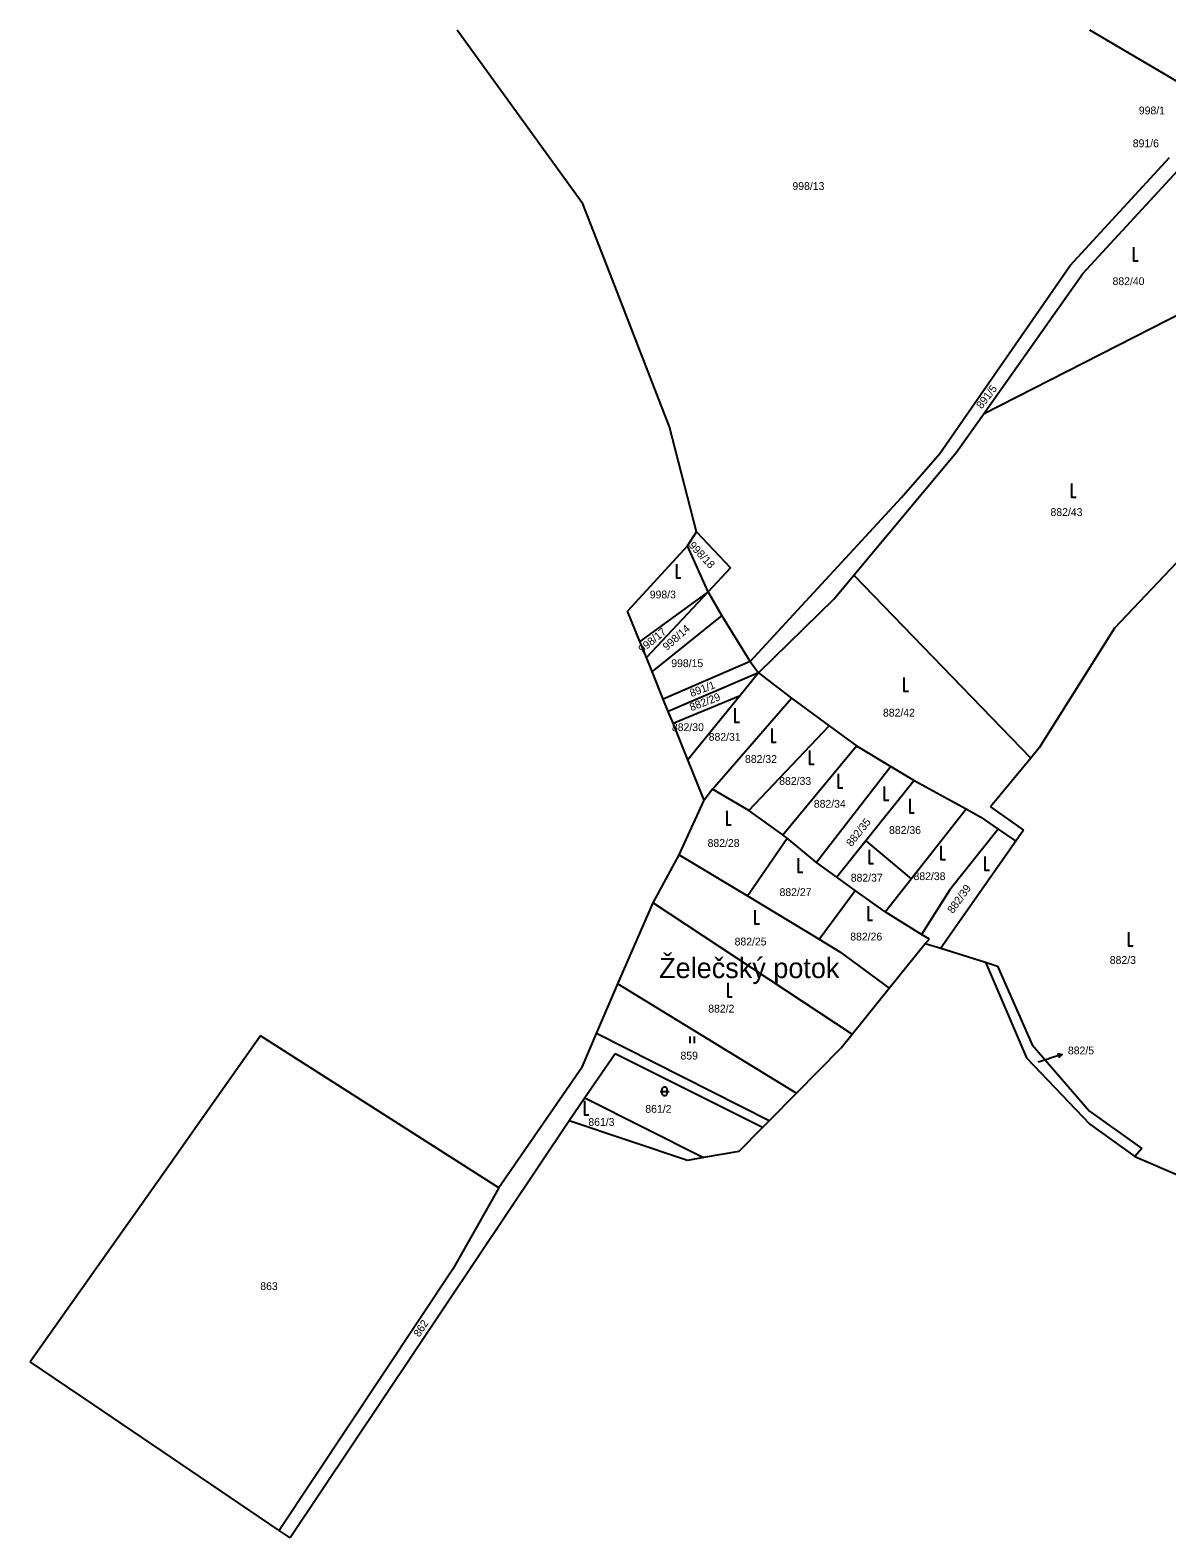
# Model space of a CAD drawing. Extents: x -801907 to -800293, y -1017000 to -1015684.
# Drawn here: x -801906.9 to -801659.6, y -1016013.2 to -1015685.2 of the extents above; entities that cross this region are included whole.
import ezdxf

# ---------------------------------------------------------------- set-up
doc = ezdxf.new("R2010")
doc.units = 0
for name, color, linetype in [('Default', 7, 'Continuous'), ('KN_HRANICE', 7, 'Continuous'), ('KN_KULTURY', 7, 'Continuous'), ('KN_PARCELY', 7, 'Continuous')]:
    doc.layers.add(name, color=color, linetype=linetype)

# ---------------------------------------------------------------- blocks, each defined once
blk = doc.blocks.new('302')
at = {"layer": 'Default'}
blk.add_lwpolyline([(0, 3), (0, 0), (1, 0)], dxfattribs=at)
blk = doc.blocks.new('306')
at = {"layer": 'Default'}
for p, q in [((-0.5, 1.5), (-0.5, 0)), ((0.5, 0), (0.5, 1.5))]:
    blk.add_line(p, q, dxfattribs=at)
blk = doc.blocks.new('316')
at = {"layer": 'Default'}
for points in [[(-1, 1), (0.27, 1), (1, 1)], [(-0.5, 1.5), (-0.4, 1.79), (-0.15, 1.97), (0.16, 1.97), (0.41, 1.79), (0.51, 1.5), (0.51, 0.5), (0.41, 0.21), (0.16, 0.03), (-0.15, 0.03), (-0.4, 0.21), (-0.5, 0.5), (-0.5, 1.5)]]:
    blk.add_lwpolyline(points, dxfattribs=at)
blk = doc.blocks.new('10292')
at = {"layer": 'Default'}
blk.add_line((0, 3), (0, 0), dxfattribs=at)
blk.add_lwpolyline([(-0.5, 2), (0, 3), (0.5, 2)], dxfattribs=at)

msp = doc.modelspace()

# ---------------------------------------------------------------- linework, layer by layer
at = {"layer": 'KN_HRANICE'}
for p, q in [((-801786.64, -1015723.02), (-801814.02, -1015685.21)), ((-801655.35, -1015697.53), (-801676.32, -1015685.21)), ((-801680.63, -1015736.45), (-801658.98, -1015712.93)), ((-801677.9, -1015738.17), (-801656.31, -1015714.79)), ((-801780.21, -1015739.56), (-801786.64, -1015723.02)), ((-801709.02, -1015777.31), (-801680.63, -1015736.45)), ((-801699.52, -1015768.78), (-801677.9, -1015738.17)), ((-801767.8, -1015771.52), (-801780.21, -1015739.56)), ((-801650.62, -1015743.8), (-801699.52, -1015768.78)), ((-801761.92, -1015794.39), (-801767.8, -1015771.52)), ((-801705.37, -1015777.06), (-801699.52, -1015768.78)), ((-801727.67, -1015803.8), (-801705.37, -1015777.06)), ((-801717.31, -1015786.87), (-801709.02, -1015777.31)), ((-801750.25, -1015822.56), (-801717.31, -1015786.87)), ((-801648.17, -1015791.2), (-801670.98, -1015815.34)), ((-801763.87, -1015797.43), (-801761.92, -1015794.39)), ((-801761.92, -1015794.39), (-801754.52, -1015802.17)), ((-801763.87, -1015797.43), (-801776.92, -1015811.64)), ((-801759.41, -1015807.4), (-801763.87, -1015797.43)), ((-801754.52, -1015802.17), (-801759.41, -1015807.4)), ((-801731.96, -1015808.95), (-801727.67, -1015803.8)), ((-801727.67, -1015803.8), (-801689.21, -1015843.62)), ((-801759.41, -1015807.4), (-801774.24, -1015818.24)), ((-801759.41, -1015807.4), (-801772.82, -1015821.74)), ((-801756.41, -1015812.56), (-801759.41, -1015807.4)), ((-801748.45, -1015825.03), (-801731.96, -1015808.95)), ((-801774.24, -1015818.24), (-801776.92, -1015811.64)), ((-801756.41, -1015812.56), (-801771.61, -1015824.73)), ((-801750.25, -1015822.56), (-801756.41, -1015812.56)), ((-801670.98, -1015815.34), (-801687.37, -1015841.38)), ((-801772.82, -1015821.74), (-801774.24, -1015818.24)), ((-801771.61, -1015824.73), (-801772.82, -1015821.74)), ((-801750.25, -1015822.56), (-801769.16, -1015830.78)), ((-801750.25, -1015822.56), (-801748.45, -1015825.03)), ((-801769.16, -1015830.78), (-801771.61, -1015824.73)), ((-801748.45, -1015825.03), (-801768.09, -1015833.42)), ((-801748.45, -1015825.03), (-801752.43, -1015829.94)), ((-801748.45, -1015825.03), (-801741.28, -1015830.56)), ((-801768.09, -1015833.42), (-801769.16, -1015830.78)), ((-801767.04, -1015836.01), (-801752.43, -1015829.94)), ((-801752.43, -1015829.94), (-801763.81, -1015843.99)), ((-801758.45, -1015850.38), (-801741.28, -1015830.56)), ((-801741.28, -1015830.56), (-801733.07, -1015836.6)), ((-801767.04, -1015836.01), (-801768.09, -1015833.42)), ((-801763.81, -1015843.99), (-801767.04, -1015836.01)), ((-801750.56, -1015854.96), (-801733.07, -1015836.6)), ((-801733.07, -1015836.6), (-801727.09, -1015840.93)), ((-801760.25, -1015852.76), (-801763.81, -1015843.99)), ((-801743.13, -1015860.29), (-801727.09, -1015840.93)), ((-801727.09, -1015840.93), (-801719.65, -1015845.45)), ((-801689.21, -1015843.62), (-801697.93, -1015854.23)), ((-801687.37, -1015841.38), (-801689.21, -1015843.62)), ((-801719.65, -1015845.45), (-801735.81, -1015866.34)), ((-801719.65, -1015845.45), (-801714.56, -1015848.5)), ((-801758.45, -1015850.38), (-801760.25, -1015852.76)), ((-801750.56, -1015854.96), (-801758.45, -1015850.38)), ((-801714.56, -1015848.5), (-801725.08, -1015861.61)), ((-801714.56, -1015848.5), (-801703.25, -1015854.6)), ((-801765.74, -1015864.63), (-801760.25, -1015852.76)), ((-801743.13, -1015860.29), (-801750.56, -1015854.96)), ((-801715.19, -1015869.83), (-801703.25, -1015854.6)), ((-801703.25, -1015854.6), (-801700.07, -1015856.45)), ((-801700.07, -1015856.45), (-801696.26, -1015859.06)), ((-801697.93, -1015854.23), (-801690.75, -1015859.25)), ((-801742.24, -1015861.02), (-801743.13, -1015860.29)), ((-801696.26, -1015859.06), (-801706.81, -1015872.26)), ((-801696.26, -1015859.06), (-801692.44, -1015861.67)), ((-801690.75, -1015859.25), (-801692.44, -1015861.67)), ((-801750.87, -1015873.59), (-801742.24, -1015861.02)), ((-801735.81, -1015866.34), (-801742.24, -1015861.02)), ((-801725.08, -1015861.61), (-801731.42, -1015869.5)), ((-801725.08, -1015861.61), (-801715.19, -1015869.83)), ((-801692.44, -1015861.67), (-801708.76, -1015884.96)), ((-801771.4, -1015875.07), (-801765.74, -1015864.63)), ((-801765.74, -1015864.63), (-801750.87, -1015873.59)), ((-801731.42, -1015869.5), (-801735.81, -1015866.34)), ((-801727.39, -1015872.4), (-801731.42, -1015869.5)), ((-801720.88, -1015877.08), (-801715.19, -1015869.83)), ((-801735.28, -1015882.99), (-801727.39, -1015872.4)), ((-801720.88, -1015877.08), (-801727.39, -1015872.4)), ((-801706.81, -1015872.26), (-801712.96, -1015881.96)), ((-801774.12, -1015881.38), (-801771.4, -1015875.07)), ((-801771.4, -1015875.07), (-801728.06, -1015903.64)), ((-801750.87, -1015873.59), (-801735.28, -1015882.99)), ((-801712.96, -1015881.96), (-801720.88, -1015877.08)), ((-801776.57, -1015887.04), (-801774.12, -1015881.38)), ((-801735.28, -1015882.99), (-801730.73, -1015885.73)), ((-801711.27, -1015883), (-801712.96, -1015881.96)), ((-801712.17, -1015883.9), (-801711.27, -1015883)), ((-801730.73, -1015885.73), (-801720.03, -1015893.67)), ((-801720.03, -1015893.67), (-801712.17, -1015883.9)), ((-801712.17, -1015883.9), (-801708.76, -1015884.96)), ((-801708.76, -1015884.96), (-801699.07, -1015888.01)), ((-801779.02, -1015892.73), (-801776.57, -1015887.04)), ((-801699.07, -1015888.01), (-801696.45, -1015888.83)), ((-801699.07, -1015888.01), (-801690.15, -1015908.8)), ((-801696.45, -1015888.83), (-801688.9, -1015905.95)), ((-801783.69, -1015903.55), (-801779.02, -1015892.73)), ((-801779.02, -1015892.73), (-801740.19, -1015916.5)), ((-801728.06, -1015903.64), (-801720.03, -1015893.67)), ((-801856.82, -1015904.02), (-801862.94, -1015912.69)), ((-801804.95, -1015937.07), (-801856.82, -1015904.02)), ((-801786.85, -1015910.87), (-801783.69, -1015903.55)), ((-801746.09, -1015922.49), (-801783.69, -1015903.55)), ((-801730.48, -1015906.65), (-801728.06, -1015903.64)), ((-801688.9, -1015905.95), (-801676.43, -1015920.39)), ((-801779.62, -1015907.91), (-801786.21, -1015917.52)), ((-801747.54, -1015923.96), (-801779.62, -1015907.91)), ((-801740.19, -1015916.5), (-801730.48, -1015906.65)), ((-801690.15, -1015908.8), (-801676.38, -1015923.23)), ((-801862.94, -1015912.69), (-801870.74, -1015923.73)), ((-801786.85, -1015910.87), (-801804.95, -1015937.07)), ((-801786.21, -1015917.52), (-801789.62, -1015922.5)), ((-801786.21, -1015917.52), (-801760.41, -1015930.53)), ((-801746.09, -1015922.49), (-801740.19, -1015916.5)), ((-801789.62, -1015922.5), (-801850.38, -1016013.25)), ((-801763.9, -1015931.14), (-801789.62, -1015922.5)), ((-801747.05, -1015923.46), (-801746.09, -1015922.49)), ((-801676.43, -1015920.39), (-801665.04, -1015928.54)), ((-801870.74, -1015923.73), (-801876.94, -1015932.5)), ((-801752.69, -1015929.18), (-801747.54, -1015923.96)), ((-801747.54, -1015923.96), (-801747.05, -1015923.46)), ((-801676.38, -1015923.23), (-801666.53, -1015930.26)), ((-801752.69, -1015929.18), (-801760.41, -1015930.53)), ((-801665.04, -1015928.54), (-801666.53, -1015930.26)), ((-801876.94, -1015932.5), (-801906.94, -1015974.96)), ((-801760.41, -1015930.53), (-801763.9, -1015931.14)), ((-801666.53, -1015930.26), (-801656.28, -1015934.67)), ((-801804.95, -1015937.07), (-801814.95, -1015954.8)), ((-801814.95, -1015954.8), (-801852.75, -1016011.65)), ((-801893.31, -1015984.19), (-801906.94, -1015974.96)), ((-801852.75, -1016011.65), (-801893.31, -1015984.19)), ((-801850.38, -1016013.25), (-801852.75, -1016011.65))]:
    msp.add_line(p, q, dxfattribs=at)
at = {"layer": 'KN_PARCELY'}
msp.add_line((-801687.61, -1015909.7), (-801685.21, -1015908.95), dxfattribs=at)

# ---------------------------------------------------------------- block references
at = {"layer": 'KN_KULTURY'}
for name, p in [('302', (-801666.83, -1015735.4)), ('302', (-801680.3, -1015786.85)), ('302', (-801766.32, -1015804.37)), ('302', (-801716.82, -1015829.03)), ('302', (-801753.6, -1015835.76)), ('302', (-801745.57, -1015840.14)), ('302', (-801737.33, -1015844.94)), ('302', (-801731.08, -1015850.05)), ('302', (-801721.07, -1015852.76)), ('302', (-801715.54, -1015855.47)), ('302', (-801755.37, -1015858.08)), ('302', (-801724.4, -1015866.53)), ('302', (-801708.77, -1015865.69)), ('302', (-801739.83, -1015868.4)), ('302', (-801699.17, -1015867.99)), ('302', (-801749.22, -1015879.67)), ('302', (-801724.61, -1015878.83)), ('302', (-801667.93, -1015884.45)), ('302', (-801755.15, -1015895.52)), ('306', (-801762.9, -1015905.64)), ('316', (-801768.88, -1015917.1)), ('302', (-801786.34, -1015921.2))]:
    msp.add_blockref(name, p, dxfattribs=at)
at = {"layer": 'KN_PARCELY', "rotation": -72.66166600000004}
msp.add_blockref('10292', (-801685.21, -1015908.95), dxfattribs=at)

# ---------------------------------------------------------------- texts
at = {"layer": 'KN_PARCELY'}
for s, height, p in [('998/1', 1.7, (-801665.68, -1015703.53)), ('891/6', 1.7, (-801667, -1015710.68)), ('998/13', 1.7, (-801741.06, -1015719.98)), ('882/40', 1.7, (-801671.4, -1015740.68)), ('882/43', 1.7, (-801684.9, -1015790.92)), ('998/3', 1.7, (-801772.11, -1015808.85)), ('998/15', 1.7, (-801767.43, -1015823.8)), ('882/42', 1.7, (-801721.36, -1015834.56)), ('882/30', 1.7, (-801767.28, -1015837.72)), ('882/31', 1.7, (-801759.28, -1015839.82)), ('882/32', 1.7, (-801751.38, -1015844.65)), ('882/33', 1.7, (-801743.94, -1015849.42)), ('882/34', 1.7, (-801736.41, -1015854.39)), ('882/36', 1.7, (-801720.04, -1015860.1)), ('882/28', 1.7, (-801759.52, -1015862.92)), ('882/37', 1.7, (-801728.37, -1015870.47)), ('882/38', 1.7, (-801714.71, -1015870.14)), ('882/27', 1.7, (-801743.87, -1015873.61)), ('882/25', 1.7, (-801753.64, -1015884.36)), ('882/26', 1.7, (-801728.48, -1015883.28)), ('Želečský potok', 4.4, (-801770.07, -1015891.46)), ('882/3', 1.7, (-801672, -1015888.38)), ('882/2', 1.7, (-801759.38, -1015898.96)), ('882/5', 1.7, (-801681.11, -1015908.06)), ('859', 1.7, (-801765.42, -1015909.18)), ('882/5', 0.1, (-801687.85, -1015909.7)), ('861/2', 1.7, (-801773.07, -1015920.77)), ('861/3', 1.7, (-801785.47, -1015923.61)), ('863', 1.7, (-801856.86, -1015959.34))]:
    msp.add_text(s, height=height, dxfattribs=at).set_placement(p)
for s, rotation, p in [('891/5', 52.598, (-801699.86, -1015767.74)), ('998/18', 313.236, (-801763.75, -1015797.43)), ('998/17', 39.076, (-801773.74, -1015820.8)), ('998/14', 41.31, (-801768.39, -1015820.28)), ('891/1', 20.626, (-801763.03, -1015830.33)), ('882/29', 21.028, (-801763.05, -1015833.41)), ('882/35', 51.623, (-801728.2, -1015862.99)), ('882/39', 54.202, (-801706.13, -1015877.54)), ('862', 56.78, (-801822.24, -1015969.7))]:
    msp.add_text(s, height=1.7, rotation=rotation, dxfattribs=at).set_placement(p)

doc.saveas('drawing.dxf')
